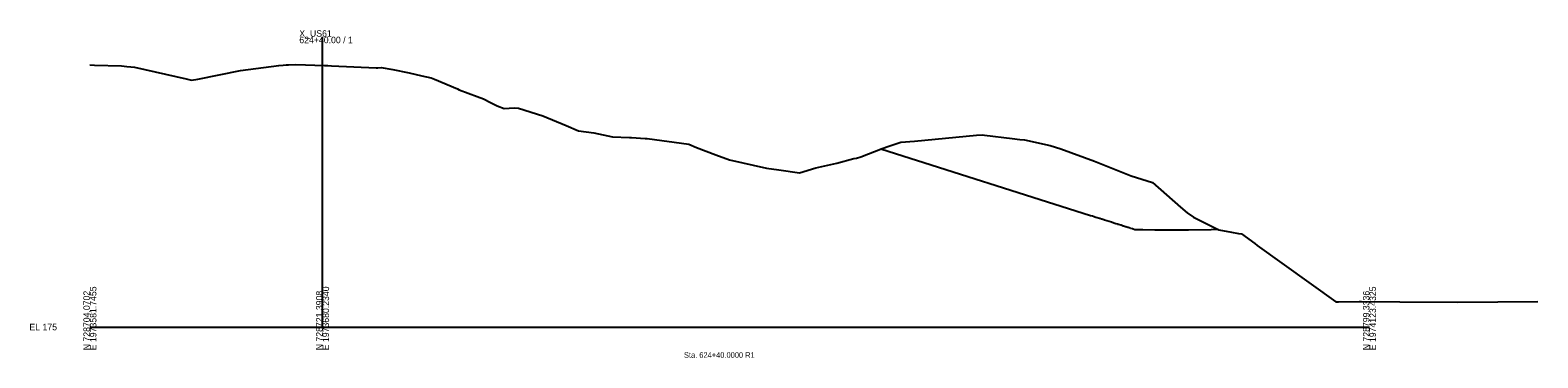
# Model space of a CAD drawing. Extents: x -26 to 1629, y -25 to 9635.
# Drawn here: x 974 to 1622, y 987 to 1128 of the extents above; entities that cross this region are included whole.
import ezdxf

# ---------------------------------------------------------------- set-up
doc = ezdxf.new("R2010")
doc.units = 0
for name, color, linetype in [('Draft_XS_Grid', 7, 'Continuous'), ('Draft_XS_Text', 7, 'Continuous'), ('DTM_X_GROUND', 7, 'Continuous'), ('XS_CELL', 7, 'Continuous'), ('XS_P_GROUND', 7, 'Continuous')]:
    doc.layers.add(name, color=color, linetype=linetype)

msp = doc.modelspace()

# ---------------------------------------------------------------- linework, layer by layer
at = {"layer": 'DTM_X_GROUND'}
msp.add_lwpolyline([(1000, 1112.83), (1002.01, 1112.77), (1013.55, 1112.4), (1015.84, 1112.22), (1017.57, 1112.09), (1019.09, 1111.91), (1041.41, 1106.83), (1043.69, 1106.24), (1046.36, 1106.78), (1064.67, 1110.48), (1081.27, 1112.61), (1083.07, 1112.78), (1084.41, 1112.91), (1085.37, 1112.95), (1088.47, 1113.07), (1100.85, 1112.62), (1102.24, 1112.57), (1103.81, 1112.49), (1123.08, 1111.57), (1123.79, 1111.63), (1125.16, 1111.77), (1130.21, 1110.89), (1137.18, 1109.4), (1142.72, 1108.15), (1146.63, 1107.24), (1148.18, 1106.7), (1158.01, 1102.55), (1158.78, 1102.18), (1166.46, 1099.32), (1169.15, 1098.29), (1172.19, 1096.68), (1175.11, 1095.26), (1178.07, 1094.07), (1182.34, 1094.4), (1184.15, 1094.21), (1194.74, 1090.91), (1204.72, 1086.84), (1209.96, 1084.53), (1216.61, 1083.65), (1224.59, 1081.89), (1231.88, 1081.56), (1232.8, 1081.58), (1238.69, 1081.24), (1239.04, 1081.18), (1239.49, 1081.11), (1257.41, 1078.73), (1260.69, 1077.33), (1269.1, 1074.07), (1274.98, 1072.01), (1290.8, 1068.42), (1296.18, 1067.68), (1305.07, 1066.38), (1312.1, 1068.55), (1321.05, 1070.57), (1328.36, 1072.58), (1329.58, 1072.72), (1331.34, 1073.24), (1340.58, 1076.88), (1343.46, 1077.9), (1348.54, 1079.53), (1354.5, 1080), (1358.9, 1080.39), (1381.1, 1082.55), (1383.47, 1082.72), (1384.56, 1082.65), (1396.39, 1081.17), (1399.69, 1080.79), (1401.77, 1080.66), (1412.78, 1078.2), (1417.41, 1076.75), (1431.84, 1071.4), (1447.6, 1065.09), (1456.8, 1062.18), (1468.77, 1051.66), (1471.65, 1049.21), (1474.32, 1047.31), (1485.24, 1041.82), (1490.72, 1040.82), (1493.73, 1040.31), (1494.95, 1040.08), (1500.68, 1035.98), (1501.78, 1035.16), (1535.48, 1010.84), (1536.66, 1010.86), (1545.52, 1011.02), (1546, 1011.02), (1546.53, 1011.03), (1563.07, 1010.84), (1587.95, 1010.74), (1622.38, 1010.95)], dxfattribs=at)
at = {"layer": 'XS_CELL'}
for p, q in [((1100, 1000), (1100, 1125)), ((1000, 1000), (1100, 1000)), ((1100, 1000), (1550, 1000))]:
    msp.add_line(p, q, dxfattribs=at)
at = {"layer": 'XS_P_GROUND'}
msp.add_lwpolyline([(1484.97, 1041.94), (1482, 1041.85), (1472.18, 1041.69), (1472.14, 1041.69), (1467.09, 1041.67), (1462.39, 1041.66), (1457.78, 1041.72), (1452.57, 1041.79), (1449.95, 1041.87), (1449.18, 1041.89), (1448.38, 1042.15), (1448.17, 1042.21), (1447.35, 1042.47), (1447.16, 1042.53), (1446.32, 1042.8), (1446.15, 1042.85), (1445.28, 1043.13), (1445.14, 1043.18), (1444.25, 1043.46), (1444.13, 1043.5), (1443.23, 1043.79), (1443.12, 1043.82), (1442.2, 1044.11), (1442.11, 1044.14), (1441.88, 1044.21), (1441.86, 1044.22), (1441.15, 1044.44), (1441.1, 1044.46), (1440.97, 1044.5), (1440.96, 1044.5), (1440.14, 1044.77), (1440.09, 1044.78), (1439.12, 1045.09), (1439.08, 1045.1), (1438.09, 1045.42), (1438.07, 1045.43), (1437.07, 1045.74), (1437.05, 1045.75), (1436.1, 1046.05), (1436.04, 1046.07), (1435.85, 1046.13), (1435.03, 1046.39), (1434.76, 1046.48), (1434.07, 1046.7), (1434.03, 1046.71), (1434.02, 1046.71), (1434, 1046.72), (1433.01, 1047.03), (1432.44, 1047.21), (1432, 1047.35), (1431.74, 1047.44), (1430.99, 1047.68), (1430.16, 1047.94), (1339.93, 1076.63)], dxfattribs=at)

# ---------------------------------------------------------------- texts
at = {"layer": 'Draft_XS_Grid'}
msp.add_text('-', height=0.0001, dxfattribs=at).set_placement((1000, 1000))
at = {"layer": 'Draft_XS_Text'}
msp.add_text('Sta. 624+40.0000 R1', height=2.4, dxfattribs=at).set_placement((1255.34, 986.75))
at = {"layer": 'XS_CELL'}
for s, p in [('X_US61', (1090, 1125)), ('624+40.00 / 1', (1090, 1122.2)), ('EL 175', (974, 998.6))]:
    msp.add_text(s, height=2.8, dxfattribs=at).set_placement(p)
for s, p in [('N 728704.0702', (1000, 990)), ('E 1973581.7455', (1002.8, 990)), ('N 728721.3908', (1100, 990)), ('E 1973680.2340', (1102.8, 990)), ('N 728799.3336', (1550, 990)), ('E 1974123.4325', (1552.8, 990))]:
    msp.add_text(s, height=2.8, rotation=90, dxfattribs=at).set_placement(p)

doc.saveas('drawing.dxf')
